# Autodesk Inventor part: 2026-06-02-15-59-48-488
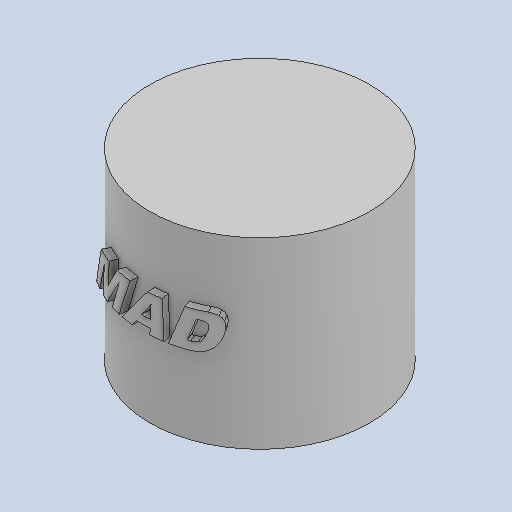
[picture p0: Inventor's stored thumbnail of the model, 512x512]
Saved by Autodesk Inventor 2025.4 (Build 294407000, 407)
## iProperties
Created: 2026-06
Part Number: 2026-06-02-15-59-48-488
Material: Generic
Document SubType Name: Modeling
Designer: AdminForWorker
Density: 1 g/cm^3
Appearance: Default
Title: LID v2
Author: AdminForWorker
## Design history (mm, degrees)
feature "Body1"
body "Solid1"
